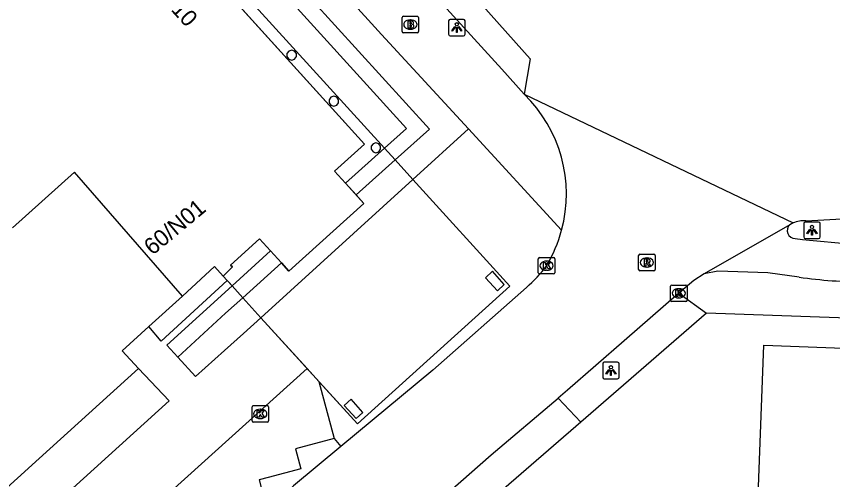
# Model space of a CAD drawing. Extents: x 161354 to 161876, y 382161 to 382804.
# Drawn here: x 161674.87 to 161724.32, y 382552.26 to 382580.37 of the extents above; entities that cross this region are included whole.
import ezdxf

# ---------------------------------------------------------------- set-up
doc = ezdxf.new("R2010")
doc.units = 0
for name, color, linetype in [('IMGEO_Brandkraan', 7, 'Continuous'), ('IMGEO_Fietspad_gesloten', 7, 'Continuous'), ('IMGEO_Groenvoorziening', 7, 'Continuous'), ('IMGEO_Kolk', 7, 'Continuous'), ('IMGEO_Lichtpunt', 7, 'Continuous'), ('IMGEO_Pand', 7, 'Continuous'), ('IMGEO_Pand_nummerreeks', 7, 'Continuous'), ('IMGEO_Pand_overbouw', 7, 'Continuous'), ('IMGEO_Parkeervlak_open', 7, 'Continuous'), ('IMGEO_Rijbaan_lokaal_gesloten', 7, 'Continuous'), ('IMGEO_Rijbaan_lokaal_open', 7, 'Continuous'), ('IMGEO_Rioolput', 7, 'Continuous'), ('IMGEO_Voetpad_gesloten', 7, 'Continuous'), ('IMGEO_Voetpad_open', 7, 'Continuous')]:
    doc.layers.add(name, color=color, linetype=linetype)

msp = doc.modelspace()

# ---------------------------------------------------------------- linework, layer by layer
at = {"layer": 'IMGEO_Brandkraan'}
for p, q in [((161698.315, 382580.372), (161699.167, 382580.372)), ((161698.24, 382579.446), (161698.24, 382580.298)), ((161698.728, 382580.152), (161698.753, 382580.152)), ((161699.241, 382580.298), (161699.241, 382579.446)), ((161698.751, 382579.592), (161698.726, 382579.592)), ((161699.167, 382579.372), (161698.315, 382579.372))]:
    msp.add_line(p, q, dxfattribs=at)
for points in [[(161698.315, 382580.372), (161699.167, 382580.372)], [(161698.24, 382579.446), (161698.24, 382580.298)], [(161698.588, 382580.072), (161698.588, 382579.672), (161698.801, 382579.672)], [(161698.819, 382580.072), (161698.588, 382580.072)], [(161698.767, 382579.991), (161698.713, 382579.991), (161698.713, 382579.915)], [(161698.713, 382579.915), (161698.766, 382579.915)], [(161699.241, 382580.298), (161699.241, 382579.446)], [(161698.775, 382579.839), (161698.713, 382579.839), (161698.713, 382579.758)], [(161698.713, 382579.758), (161698.775, 382579.758)], [(161699.167, 382579.372), (161698.315, 382579.372)]]:
    msp.add_lwpolyline(points, dxfattribs=at)
for centre, radius, start, end in [((161698.317, 382580.296), 0.0765, 91.552, 178.448), ((161698.317, 382580.296), 0.0765, 91.552, 178.448), ((161699.165, 382580.296), 0.0765, 1.552, 88.448), ((161699.165, 382580.296), 0.0765, 1.552, 88.448), ((161698.768, 382579.953), 0.0379, 267.8285, 90.9355), ((161698.823, 382579.927), 0.145, 59.4692, 91.5367), ((161698.848, 382579.974), 0.0922, 285.5137, 58.1501), ((161698.853, 382579.782), 0.105, 301.3115, 78.989), ((161698.317, 382579.448), 0.0765, 181.552, 268.448), ((161698.317, 382579.448), 0.0765, 181.552, 268.448), ((161698.776, 382579.798), 0.0404, 269.8759, 90.5077), ((161698.807, 382579.923), 0.251, 268.6676, 293.5347), ((161699.165, 382579.448), 0.0765, 271.552, 358.448), ((161699.165, 382579.448), 0.0765, 271.552, 358.448)]:
    msp.add_arc(centre, radius, start, end, dxfattribs=at)
for centre, major_axis, ratio, start_param, end_param in [((161698.727, 382579.872), (-0.387, 0.002), 0.722429, 4.712389, 7.853982), ((161698.752, 382579.872), (-0.39, 0.002), 0.717154, 1.570796, 4.712389)]:
    msp.add_ellipse(centre, major_axis=major_axis, ratio=ratio, start_param=start_param, end_param=end_param, dxfattribs=at)
at = {"layer": 'IMGEO_Fietspad_gesloten'}
for points in [[(161645.871, 382640.073), (161646.136, 382639.799), (161650.877, 382635.381), (161656.463, 382629.372), (161661.71, 382623.972), (161676.15, 382608.16), (161698.844, 382583.161), (161704.285, 382577.171), (161705.643, 382575.646)], [(161722.297, 382564.547), (161720.388, 382564.809), (161717.357, 382564.904), (161716.541, 382564.759)]]:
    msp.add_lwpolyline(points, dxfattribs=at)
for centre, radius, start, end in [((161722.051, 382567.372), 0.483, 132.6135, 270.6116), ((161733.929, 382676.424), 110.176, 263.81352, 267.45559), ((161726.527, 382594.945), 30.691, 262.0772, 269.5474)]:
    msp.add_arc(centre, radius, start, end, dxfattribs=at)
at = {"layer": 'IMGEO_Groenvoorziening'}
msp.add_lwpolyline([(161688.589, 382563.302), (161687.547, 382562.36), (161684.649, 382559.706)], dxfattribs=at)
at = {"layer": 'IMGEO_Kolk'}
for p, q in [((161706.491, 382564.819), (161706.491, 382565.671)), ((161706.566, 382565.745), (161707.418, 382565.745)), ((161707.492, 382565.671), (161707.492, 382564.819)), ((161706.979, 382565.525), (161707.004, 382565.525)), ((161707.418, 382564.745), (161706.566, 382564.745)), ((161707.002, 382564.965), (161706.977, 382564.965)), ((161714.577, 382564.072), (161715.429, 382564.072)), ((161714.502, 382563.146), (161714.502, 382563.998)), ((161714.99, 382563.852), (161715.015, 382563.852)), ((161715.503, 382563.998), (161715.503, 382563.146)), ((161715.429, 382563.072), (161714.577, 382563.072)), ((161715.013, 382563.292), (161714.988, 382563.292)), ((161689.147, 382555.829), (161689.147, 382556.681)), ((161689.222, 382556.755), (161690.074, 382556.755)), ((161690.148, 382556.681), (161690.148, 382555.829)), ((161689.635, 382556.535), (161689.66, 382556.535)), ((161690.074, 382555.755), (161689.222, 382555.755)), ((161689.658, 382555.975), (161689.633, 382555.975))]:
    msp.add_line(p, q, dxfattribs=at)
for points in [[(161706.491, 382564.819), (161706.491, 382565.671)], [(161706.566, 382565.745), (161707.418, 382565.745)], [(161707.492, 382565.671), (161707.492, 382564.819)], [(161706.812, 382565.445), (161706.935, 382565.445), (161706.935, 382565.294), (161707.065, 382565.445), (161707.229, 382565.445), (161707.083, 382565.294), (161707.236, 382565.045), (161707.084, 382565.045), (161706.999, 382565.209), (161706.935, 382565.142), (161706.935, 382565.045), (161706.812, 382565.045), (161706.812, 382565.445)], [(161707.418, 382564.745), (161706.566, 382564.745)], [(161714.577, 382564.072), (161715.429, 382564.072)], [(161714.502, 382563.146), (161714.502, 382563.998)], [(161714.823, 382563.772), (161714.946, 382563.772), (161714.946, 382563.621), (161715.076, 382563.772), (161715.24, 382563.772), (161715.094, 382563.621), (161715.247, 382563.372), (161715.095, 382563.372), (161715.01, 382563.536), (161714.946, 382563.469), (161714.946, 382563.372), (161714.823, 382563.372), (161714.823, 382563.772)], [(161715.503, 382563.998), (161715.503, 382563.146)], [(161715.429, 382563.072), (161714.577, 382563.072)], [(161689.147, 382555.829), (161689.147, 382556.681)], [(161689.222, 382556.755), (161690.074, 382556.755)], [(161690.148, 382556.681), (161690.148, 382555.829)], [(161689.468, 382556.455), (161689.591, 382556.455), (161689.591, 382556.304), (161689.721, 382556.455), (161689.885, 382556.455), (161689.739, 382556.304), (161689.892, 382556.055), (161689.74, 382556.055), (161689.655, 382556.219), (161689.591, 382556.152), (161689.591, 382556.055), (161689.468, 382556.055), (161689.468, 382556.455)], [(161690.074, 382555.755), (161689.222, 382555.755)]]:
    msp.add_lwpolyline(points, dxfattribs=at)
for centre, start, end in [((161706.568, 382565.669), 91.552, 178.448), ((161706.568, 382565.669), 91.552, 178.448), ((161707.416, 382565.669), 1.552, 88.448), ((161707.416, 382565.669), 1.552, 88.448), ((161706.568, 382564.821), 181.552, 268.448), ((161706.568, 382564.821), 181.552, 268.448), ((161707.416, 382564.821), 271.552, 358.448), ((161707.416, 382564.821), 271.552, 358.448), ((161714.579, 382563.996), 91.552, 178.448), ((161714.579, 382563.996), 91.552, 178.448), ((161715.427, 382563.996), 1.552, 88.448), ((161715.427, 382563.996), 1.552, 88.448), ((161714.579, 382563.148), 181.552, 268.448), ((161714.579, 382563.148), 181.552, 268.448), ((161715.427, 382563.148), 271.552, 358.448), ((161715.427, 382563.148), 271.552, 358.448), ((161689.224, 382556.679), 91.552, 178.448), ((161689.224, 382556.679), 91.552, 178.448), ((161690.072, 382556.679), 1.552, 88.448), ((161690.072, 382556.679), 1.552, 88.448), ((161689.224, 382555.831), 181.552, 268.448), ((161689.224, 382555.831), 181.552, 268.448), ((161690.072, 382555.831), 271.552, 358.448), ((161690.072, 382555.831), 271.552, 358.448)]:
    msp.add_arc(centre, 0.0765, start, end, dxfattribs=at)
for centre, major_axis, ratio, start_param, end_param in [((161706.978, 382565.245), (-0.387, 0.002), 0.722429, 4.712389, 7.853982), ((161707.003, 382565.245), (-0.39, 0.002), 0.717154, 1.570796, 4.712389), ((161714.989, 382563.572), (-0.387, 0.002), 0.722429, 4.712389, 7.853982), ((161715.014, 382563.572), (-0.39, 0.002), 0.717154, 1.570796, 4.712389), ((161689.634, 382556.255), (-0.387, 0.002), 0.722429, 4.712389, 7.853982), ((161689.659, 382556.255), (-0.39, 0.002), 0.717154, 1.570796, 4.712389)]:
    msp.add_ellipse(centre, major_axis=major_axis, ratio=ratio, start_param=start_param, end_param=end_param, dxfattribs=at)
at = {"layer": 'IMGEO_Lichtpunt'}
for p, q in [((161701.056, 382580.091), (161701.056, 382579.284)), ((161701.056, 382580.091), (161701.056, 382579.284)), ((161701.958, 382580.186), (161701.15, 382580.186)), ((161701.958, 382580.186), (161701.15, 382580.186)), ((161702.052, 382579.284), (161702.052, 382580.091)), ((161702.052, 382579.284), (161702.052, 382580.091)), ((161701.15, 382579.19), (161701.958, 382579.19)), ((161701.15, 382579.19), (161701.958, 382579.19)), ((161722.572, 382567.798), (161722.572, 382566.991)), ((161722.572, 382567.798), (161722.572, 382566.991)), ((161723.474, 382567.893), (161722.666, 382567.893)), ((161723.474, 382567.893), (161722.666, 382567.893)), ((161723.568, 382566.991), (161723.568, 382567.798)), ((161723.568, 382566.991), (161723.568, 382567.798)), ((161722.666, 382566.897), (161723.474, 382566.897)), ((161722.666, 382566.897), (161723.474, 382566.897)), ((161710.39, 382559.291), (161710.39, 382558.484)), ((161710.39, 382559.291), (161710.39, 382558.484)), ((161711.292, 382559.386), (161710.484, 382559.386)), ((161711.292, 382559.386), (161710.484, 382559.386)), ((161711.386, 382558.484), (161711.386, 382559.291)), ((161711.386, 382558.484), (161711.386, 382559.291)), ((161710.484, 382558.39), (161711.292, 382558.39)), ((161710.484, 382558.39), (161711.292, 382558.39))]:
    msp.add_line(p, q, dxfattribs=at)
for points in [[(161701.43, 382579.755), (161701.469, 382579.727), (161701.281, 382579.465), (161701.243, 382579.492), (161701.43, 382579.755)], [(161701.532, 382579.707), (161701.579, 382579.707), (161701.579, 382579.385), (161701.532, 382579.385), (161701.532, 382579.707)], [(161701.642, 382579.727), (161701.68, 382579.754), (161701.867, 382579.492), (161701.828, 382579.464), (161701.642, 382579.727)], [(161722.946, 382567.462), (161722.985, 382567.434), (161722.797, 382567.172), (161722.759, 382567.199), (161722.946, 382567.462)], [(161723.048, 382567.414), (161723.095, 382567.414), (161723.095, 382567.092), (161723.048, 382567.092), (161723.048, 382567.414)], [(161723.158, 382567.434), (161723.196, 382567.461), (161723.383, 382567.199), (161723.344, 382567.171), (161723.158, 382567.434)], [(161710.764, 382558.955), (161710.803, 382558.927), (161710.615, 382558.665), (161710.577, 382558.692), (161710.764, 382558.955)], [(161710.866, 382558.907), (161710.913, 382558.907), (161710.913, 382558.585), (161710.866, 382558.585), (161710.866, 382558.907)], [(161710.976, 382558.927), (161711.014, 382558.954), (161711.201, 382558.692), (161711.162, 382558.664), (161710.976, 382558.927)]]:
    msp.add_lwpolyline(points, dxfattribs=at)
for centre in [(161701.555, 382579.889), (161723.071, 382567.596), (161710.889, 382559.089)]:
    msp.add_circle(centre, 0.0994, dxfattribs=at)
for centre, start, end in [((161701.15, 382580.091), 90, 180), ((161701.15, 382580.091), 90, 180), ((161701.958, 382580.091), 0, 90), ((161701.958, 382580.091), 0, 90), ((161701.15, 382579.284), 180, 270), ((161701.15, 382579.284), 180, 270), ((161701.958, 382579.284), 270, 0), ((161701.958, 382579.284), 270, 360), ((161722.666, 382567.798), 90, 180), ((161722.666, 382567.798), 90, 180), ((161723.474, 382567.798), 0, 90), ((161723.474, 382567.798), 0, 90), ((161722.666, 382566.991), 180, 270), ((161722.666, 382566.991), 180, 270), ((161723.474, 382566.991), 270, 0), ((161723.474, 382566.991), 270, 360), ((161710.484, 382559.291), 90, 180), ((161710.484, 382559.291), 90, 180), ((161711.292, 382559.291), 0, 90), ((161711.292, 382559.291), 0, 90), ((161710.484, 382558.484), 180, 270), ((161710.484, 382558.484), 180, 270), ((161711.292, 382558.484), 270, 0), ((161711.292, 382558.484), 270, 360)]:
    msp.add_arc(centre, 0.0946, start, end, dxfattribs=at)
at = {"layer": 'IMGEO_Pand'}
for points in [[(161694.808, 382570.257), (161694.144, 382570.989), (161695.962, 382572.626), (161678.502, 382591.938), (161675.871, 382594.848)], [(161691.551, 382577.722), (161691.727, 382577.779), (161691.836, 382577.929), (161691.836, 382578.115), (161691.727, 382578.265), (161691.551, 382578.322), (161691.375, 382578.265), (161691.266, 382578.115), (161691.266, 382577.929), (161691.375, 382577.779), (161691.551, 382577.722)], [(161694.107, 382574.921), (161694.283, 382574.978), (161694.392, 382575.128), (161694.392, 382575.314), (161694.283, 382575.464), (161694.107, 382575.521), (161693.931, 382575.464), (161693.822, 382575.314), (161693.822, 382575.128), (161693.931, 382574.978), (161694.107, 382574.921)], [(161696.653, 382572.101), (161696.829, 382572.158), (161696.938, 382572.308), (161696.938, 382572.494), (161696.829, 382572.644), (161696.653, 382572.701), (161696.477, 382572.644), (161696.368, 382572.494), (161696.368, 382572.308), (161696.477, 382572.158), (161696.653, 382572.101)], [(161684.928, 382563.407), (161678.388, 382570.921), (161674.636, 382567.532)], [(161695.455, 382569.543), (161694.808, 382570.257)], [(161690.926, 382565.414), (161691.385, 382564.907), (161695.922, 382569.028), (161695.455, 382569.543)], [(161687.408, 382564.618), (161687.965, 382565.168), (161687.847, 382565.287), (161689.608, 382566.87), (161690.27, 382566.139)], [(161690.27, 382566.139), (161690.926, 382565.414)], [(161684.928, 382563.407), (161686.88, 382565.188), (161687.408, 382564.618)], [(161704.011, 382563.721), (161704.425, 382564.101), (161703.722, 382564.905), (161703.294, 382564.513), (161704.011, 382563.721)], [(161682.89, 382561.547), (161684.928, 382563.407)], [(161682.89, 382561.547), (161681.273, 382560.072), (161682.265, 382559.016)], [(161735.075, 382528.457), (161734.18, 382530.69), (161749.331, 382536.762), (161748.369, 382539.161), (161750.406, 382539.978), (161752.228, 382539.889), (161752.332, 382542.029), (161724.511, 382543.072), (161719.514, 382543.259), (161720.16, 382560.416), (161766.754, 382558.659), (161766.519, 382552.424), (161766.277, 382545.989), (161766.108, 382541.512), (161761.112, 382541.699), (161755.002, 382541.928), (161754.713, 382535.995)], [(161643.672, 382523.978), (161676.253, 382553.55), (161682.265, 382559.016)], [(161695.452, 382555.969), (161695.866, 382556.346), (161695.158, 382557.143), (161694.726, 382556.762), (161695.452, 382555.969)]]:
    msp.add_lwpolyline(points, dxfattribs=at)
at = {"layer": 'IMGEO_Pand_overbouw'}
msp.add_lwpolyline([(161675.871, 382594.848), (161695.962, 382572.626), (161694.144, 382570.989), (161694.808, 382570.257), (161695.922, 382569.028), (161691.385, 382564.907), (161690.926, 382565.414), (161690.27, 382566.139), (161689.608, 382566.87), (161687.847, 382565.287), (161687.965, 382565.168), (161687.408, 382564.618), (161687.648, 382564.351), (161687.688, 382564.306), (161687.758, 382564.227), (161687.944, 382564.02), (161688.589, 382563.302), (161689.676, 382562.09), (161695.542, 382555.644), (161704.759, 382563.996), (161698.891, 382570.474), (161697.816, 382571.661), (161697.168, 382572.377), (161680.52, 382590.719)], dxfattribs=at)
at = {"layer": 'IMGEO_Parkeervlak_open'}
msp.add_lwpolyline([(161694.116, 382554.765), (161691.774, 382554.142), (161692.098, 382552.924), (161690.119, 382552.398), (161689.571, 382552.252), (161689.864, 382551.148), (161687.527, 382550.526), (161687.9, 382549.123), (161685.689, 382548.535), (161685.975, 382547.461), (161683.612, 382546.833), (161683.948, 382545.572), (161681.511, 382544.924), (161681.789, 382543.88), (161679.495, 382543.27), (161679.825, 382542.031), (161677.519, 382541.417), (161677.813, 382540.311), (161675.339, 382539.653), (161675.696, 382538.314), (161673.531, 382537.738)], dxfattribs=at)
at = {"layer": 'IMGEO_Rijbaan_lokaal_gesloten'}
for points in [[(161575.378, 382721.548), (161577.619, 382719.049), (161589.767, 382705.692), (161601.665, 382692.722), (161616.607, 382676.142), (161624.391, 382667.348), (161636.242, 382654.182), (161636.579, 382653.807), (161653.899, 382634.564), (161673.989, 382613.712), (161706.007, 382577.787), (161705.643, 382575.646)], [(161705.643, 382575.646), (161721.925, 382567.837)], [(161722.7, 382567.959), (161726.721, 382568.193), (161728.883, 382568.336)], [(161721.724, 382567.727), (161716.541, 382564.759)], [(161721.925, 382567.837), (161721.724, 382567.727)], [(161716.541, 382564.759), (161715.917, 382564.341), (161715.002, 382563.572)], [(161705.768, 382563.927), (161700.093, 382558.908), (161694.524, 382554.274)], [(161715.002, 382563.572), (161711.696, 382560.686), (161708.262, 382557.69), (161707.699, 382557.212)], [(161701.128, 382551.574), (161703.639, 382553.768), (161707.699, 382557.212)], [(161694.524, 382554.274), (161691.651, 382551.884), (161690.206, 382550.598), (161681.712, 382543.025), (161666.712, 382529.643)]]:
    msp.add_lwpolyline(points, dxfattribs=at)
for centre, radius, start, end in [((161699.725, 382569.59), 8.468, 344.9712, 45.6612), ((161722.54, 382566.454), 1.514, 83.9294, 113.9627), ((161699.69, 382569.605), 8.505, 329.164, 344.9353), ((161700.456, 382570.093), 8.138, 310.7475, 323.4414)]:
    msp.add_arc(centre, radius, start, end, dxfattribs=at)
at = {"layer": 'IMGEO_Rijbaan_lokaal_open'}
for points in [[(161698.891, 382570.474), (161689.676, 382562.09)], [(161698.891, 382570.474), (161704.759, 382563.996), (161695.542, 382555.644), (161693.197, 382558.221)], [(161687.648, 382564.351), (161683.638, 382560.672), (161682.89, 382561.547)], [(161687.944, 382564.02), (161687.648, 382564.351)], [(161684.649, 382559.706), (161683.982, 382560.43), (161687.944, 382564.02)], [(161684.649, 382559.706), (161685.729, 382558.534), (161687.482, 382560.098), (161688.624, 382561.141), (161689.676, 382562.09)], [(161692.48, 382559.009), (161689.676, 382562.09)], [(161682.265, 382559.016), (161684.128, 382557.046), (161652.099, 382527.995)], [(161653.308, 382523.528), (161654.315, 382524.377), (161662.915, 382532.2), (161671.874, 382540.317), (161680.506, 382548.198), (161692.48, 382559.009)], [(161692.48, 382559.009), (161693.197, 382558.221)]]:
    msp.add_lwpolyline(points, dxfattribs=at)
at = {"layer": 'IMGEO_Rioolput'}
for p, q in [((161712.569, 382565.012), (161712.569, 382565.864)), ((161712.644, 382565.938), (161713.496, 382565.938)), ((161713.057, 382565.718), (161713.082, 382565.718)), ((161713.57, 382565.864), (161713.57, 382565.012)), ((161713.08, 382565.158), (161713.055, 382565.158)), ((161713.496, 382564.938), (161712.644, 382564.938))]:
    msp.add_line(p, q, dxfattribs=at)
for points in [[(161712.569, 382565.012), (161712.569, 382565.864)], [(161712.644, 382565.938), (161713.496, 382565.938)], [(161713.158, 382565.636), (161712.906, 382565.638), (161712.906, 382565.238)], [(161713.084, 382565.557), (161713.03, 382565.557), (161713.03, 382565.476)], [(161713.57, 382565.864), (161713.57, 382565.012)], [(161712.906, 382565.238), (161713.03, 382565.238), (161713.03, 382565.4), (161713.041, 382565.4)], [(161713.03, 382565.476), (161713.082, 382565.476)], [(161713.088, 382565.371), (161713.159, 382565.238), (161713.299, 382565.238), (161713.234, 382565.364)], [(161713.496, 382564.938), (161712.644, 382564.938)]]:
    msp.add_lwpolyline(points, dxfattribs=at)
for centre, radius, start, end in [((161712.646, 382565.862), 0.0765, 91.552, 178.448), ((161712.646, 382565.862), 0.0765, 91.552, 178.448), ((161713.09, 382565.461), 0.0964, 77.0061, 93.1865), ((161713.104, 382565.518), 0.0378, 276.6634, 79.6772), ((161713.157, 382565.526), 0.109, 350.3612, 89.416), ((161713.494, 382565.862), 0.0765, 1.552, 88.448), ((161713.494, 382565.862), 0.0765, 1.552, 88.448), ((161713.04, 382565.347), 0.0533, 26.0293, 88.6989), ((161713.066, 382565.665), 0.19, 274.7715, 282.9687), ((161713.155, 382565.526), 0.112, 277.5842, 350.9817), ((161713.139, 382565.311), 0.108, 29.5134, 73.7905), ((161712.646, 382565.014), 0.0765, 181.552, 268.448), ((161712.646, 382565.014), 0.0765, 181.552, 268.448), ((161713.494, 382565.014), 0.0765, 271.552, 358.448), ((161713.494, 382565.014), 0.0765, 271.552, 358.448)]:
    msp.add_arc(centre, radius, start, end, dxfattribs=at)
for centre, major_axis, ratio, start_param, end_param in [((161713.056, 382565.438), (-0.387, 0.002), 0.722429, 4.712389, 7.853982), ((161713.081, 382565.438), (-0.39, 0.002), 0.717154, 1.570796, 4.712389)]:
    msp.add_ellipse(centre, major_axis=major_axis, ratio=ratio, start_param=start_param, end_param=end_param, dxfattribs=at)
at = {"layer": 'IMGEO_Voetpad_gesloten'}
for points in [[(161697.816, 382571.661), (161699.891, 382573.522), (161681.259, 382594.056), (161681.066, 382594.264), (161680.342, 382593.591), (161681.865, 382591.932)], [(161697.168, 382572.377), (161698.504, 382573.577), (161681.865, 382591.932)], [(161697.168, 382572.377), (161694.808, 382570.257)], [(161697.816, 382571.661), (161697.168, 382572.377)], [(161695.455, 382569.543), (161697.816, 382571.661)], [(161687.944, 382564.02), (161690.27, 382566.139)], [(161688.589, 382563.302), (161690.926, 382565.414)], [(161687.944, 382564.02), (161688.589, 382563.302)]]:
    msp.add_lwpolyline(points, dxfattribs=at)
at = {"layer": 'IMGEO_Voetpad_open'}
for points in [[(161679.75, 382598.28), (161682.518, 382595.225), (161696.997, 382579.273), (161702.259, 382573.539)], [(161680.52, 382590.719), (161697.168, 382572.377)], [(161702.259, 382573.539), (161698.891, 382570.474)], [(161702.259, 382573.539), (161707.903, 382567.394)], [(161697.816, 382571.661), (161698.891, 382570.474)], [(161687.408, 382564.618), (161687.648, 382564.351)], [(161715.002, 382563.572), (161716.681, 382562.374)], [(161689.676, 382562.09), (161688.589, 382563.302)], [(161716.681, 382562.374), (161709.058, 382555.75)], [(161782.001, 382556.605), (161781.188, 382558.978), (161780.231, 382559.421), (161779.298, 382559.715), (161776.187, 382560.249), (161770.93, 382560.454), (161716.681, 382562.374)], [(161693.197, 382558.221), (161694.116, 382554.765)], [(161707.699, 382557.212), (161709.058, 382555.75)], [(161709.058, 382555.75), (161702.444, 382550.002)], [(161694.116, 382554.765), (161694.524, 382554.274)]]:
    msp.add_lwpolyline(points, dxfattribs=at)

# ---------------------------------------------------------------- texts
at = {"layer": 'IMGEO_Pand_nummerreeks'}
for s, rotation, p in [('8-10', 312.1956, (161683.397, 382581.637)), ('60/N01', 39.7743, (161683.119, 382565.839))]:
    msp.add_text(s, height=1, rotation=rotation, dxfattribs=at).set_placement(p)

doc.saveas('drawing.dxf')
